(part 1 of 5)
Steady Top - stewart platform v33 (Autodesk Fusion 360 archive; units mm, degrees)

design "Steady Top - stewart platform" references "L servo horn", "Meanwell RSP-150-7.5", "815 Servo Driver 16 Channel", "KBRM_10_2", "KBRM_05_1", "fab dev board 2", "sunfounder_20kgSLDPRT", "GZRM_06_IG_6", "PCB mount", "KCRM_10_3", "R servo horn", "SERVO ARM HORN WITH FASTENERS", "BNO085 STEMMA QT", "Ball joint"
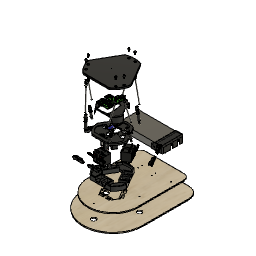
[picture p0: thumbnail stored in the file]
description: Part Number
part number: 7010K167_Power Supply
part number: 91292A191_18-8 Stainless Steel Socket Head Screw
description: STEP AP214
part number: 2025_05_17_16_39_25_0877
component_insert "Component Insert1"
position "Position1"
component_insert "Component Insert2"
position "Position2"
step "00000000-0000-0000-0000-000000000000" TotalAngle 360
sketch "Sketch1" plane through (0, 0, 0) normal (0, 0, 1) x axis (1, 0, 0)
  line L1 (25.1, -61.9) -> (-25.1, -61.9)
  line L2 (25.1, -33.65) -> (25.1, -61.9)
  line L3 (-25.1, -33.65) -> (25.1, -33.65)
  line L4 (-25.1, -61.9) -> (-25.1, -33.65)
  line L5 (0, 0) -> (0, -33.65)
  line L6 (-4.975, -61.9) -> (4.975, -61.9)
  line L7 (-4.975, -5.4) -> (-4.975, -61.9)
  line L8 (4.975, -5.4) -> (-4.975, -5.4)
  line L9 (4.975, -61.9) -> (4.975, -5.4)
  line L10 (-4.975, -5.4) -> (4.975, -61.9)
  line L11 (4.975, -5.4) -> (-4.975, -61.9)
  line L12 (-50.6793, -61.9) -> (-25.1, -61.9)
  line L13 (50.6793, -61.9) -> (25.1, -61.9)
  line L14 (-54.1368, -58.9) -> (54.1368, -58.9)
  line L15 (78.0773, -17.4338) -> (23.9405, 76.3338)
  line L16 (-23.9405, 76.3338) -> (-78.0773, -17.4338)
  line L17 (78.9466, -12.9395) -> (66.157, 9.2128)
  line L18 (28.2673, 74.8395) -> (41.057, 52.6872)
  line L19 (2.189, 7.0085) -> (7.164, -1.6085)
  line L20 (51.1195, 35.2585) -> (2.189, 7.0085)
  line L21 (7.164, -1.6085) -> (56.0945, 26.6415)
  line L22 (56.0945, 26.6415) -> (51.1195, 35.2585)
  line L23 (16.5918, 38.5622) -> (41.057, 52.6872)
  line L24 (66.157, 9.2128) -> (41.6918, -4.9122)
  line L25 (41.6918, -4.9122) -> (16.5918, 38.5622)
  line L26 (-28.2673, 74.8395) -> (-41.057, 52.6872)
  line L27 (-78.9466, -12.9395) -> (-66.157, 9.2128)
  line L28 (-7.164, -1.6085) -> (-2.189, 7.0085)
  line L29 (-56.0945, 26.6415) -> (-7.164, -1.6085)
  line L30 (-2.189, 7.0085) -> (-51.1195, 35.2585)
  line L31 (-51.1195, 35.2585) -> (-56.0945, 26.6415)
  line L32 (-41.6918, -4.9122) -> (-66.157, 9.2128)
  line L33 (-41.057, 52.6872) -> (-16.5918, 38.5622)
  line L34 (-16.5918, 38.5622) -> (-41.6918, -4.9122)
  line L35 (41.057, 52.6872) -> (66.157, 9.2128)
  line L36 (-66.157, 9.2128) -> (-41.057, 52.6872)
  circle C1 centre (0, 0) radius 80
  point P1 (0, 0)
  point P2 (0, 0)
  point P7 (0, -33.65)
  point P8 (0, 0)
  point P14 (0, -33.65)
  point P10 (4.975, -61.9)
  point P15 (-50.6793, -61.9)
  point P16 (50.6793, -61.9)
  point P17 (54.1368, -58.9)
  point P18 (-54.1368, -58.9)
  point P5 (25.1, -33.65)
  point P6 (-25.1, -33.65)
  point P9 (0, 0)
  point P12 (-4.975, -5.4)
  point P13 (4.975, -5.4)
  coincident P1 P2
  horizontal L1
  vertical L2
  horizontal L3
  vertical L4
  midpoint L3 P7
  coincident P1 P8
  vertical L5
  horizontal L6
  perpendicular L6 L7
  parallel L6 L8
  parallel L7 L9
  coincident L10 P14
  coincident L11 P14
  coincident L1 P10
  coincident P7 P14
  coincident C1 P15
  perpendicular L4 L12
  coincident C1 P16
  perpendicular L2 L13
  coincident C1 P17
  coincident C1 P18
  parallel L13 L14
  dimension "d3" diameter C1 = 160
  dimension "d4" distance P5 P6 = 50.2
  dimension "d5" distance L1 P8 = 61.9
  dimension "d6" distance L3 P9 = 33.65
  dimension "d7" distance P12 P13 = 9.95
  dimension "d8" distance L12 L14 = 3
  dimension "d10" C-Pattern1-Angle = 360
extrude "Extrude1" new body sketch "Sketch1" profile of C1 L1 L2 L3 L4 L5 L6 L7 L8 L9 L12 L13 L14 L15 L16 L17 L18 L19 L20 L21 L22 L23 L24 L25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 against normal blind 9.75
extrude "Extrude2" sketch "Sketch1" profile of C1 L1 L2 L3 L4 L5 L6 L7 L8 L9 L12 L13 L14 L15 L16 L17 L18 L19 L20 L21 L22 L23 L24 L25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 blind -9
shell "Shell1" innerThickness 5
sketch "Sketch2" plane through (0, 0, -9.75) normal (0, 0, 1) x axis (-1, 0, 0)
  line L1 (78.9466, 12.9395) -> (28.2673, -74.8395)
  line L2 (-50.6793, 61.9) -> (50.6793, 61.9)
  line L3 (-28.2673, -74.8395) -> (-78.9466, 12.9395)
  line L4 (-50.8068, 0) -> (-25.4034, 44)
  line L5 (-25.4034, -44) -> (-50.8068, 0)
  line L6 (25.4034, -44) -> (-25.4034, -44)
  line L7 (50.8068, 0) -> (25.4034, -44)
  line L8 (25.4034, 44) -> (50.8068, 0)
  line L9 (-25.4034, 44) -> (25.4034, 44)
  arc A1 centre (0, 0) radius 80 clockwise from (28.2673, -74.8395) to (-28.2673, -74.8395)
  arc A2 centre (0, 0) radius 80 clockwise from (50.6793, 61.9) to (78.9466, 12.9395)
  arc A3 centre (0, 0) radius 80 clockwise from (-78.9466, 12.9395) to (-50.6793, 61.9)
  point P4 (0, 0)
  point P15 (0, 0)
  coincident P4 P15
  dimension "d17" distance P4 L9 = 44
extrude "Extrude3" cut sketch "Sketch2" profile of L4 L5 L6 L7 L8 L9 against normal blind 9
combine "Combine1"
extrude "Extrude4" add of existing geometry to an object
sketch "Sketch3" plane through (0, -61.9, 0) normal (0, -1, 0) x axis (1, 0, 0)
  line L1 (-4.975, 0) -> (4.975, 0)
  line L2 (-4.975, -9.75) -> (-4.975, 0)
  line L3 (-25.1, -9.75) -> (-4.975, -9.75)
  line L4 (-25.1, 0) -> (-25.1, -9.75)
  line L5 (-50.6793, 0) -> (-25.1, 0)
  line L6 (-50.6793, -18.75) -> (-50.6793, 0)
  line L7 (50.6793, -18.75) -> (-50.6793, -18.75)
  line L8 (50.6793, 0) -> (50.6793, -18.75)
  line L9 (25.1, 0) -> (50.6793, 0)
  line L10 (25.1, -9.75) -> (25.1, 0)
  line L11 (4.975, -9.75) -> (25.1, -9.75)
  line L12 (4.975, 0) -> (4.975, -9.75)
  arc A1 centre (-19.75, 34.7974) radius 2.15 clockwise from (-18.85, 36.75) to (-20.65, 36.75)
  arc A2 centre (-19.75, 34.7974) radius 2.15 clockwise from (-18.85, 36.75) to (-20.65, 36.75)
  arc A3 centre (-10.25, 34.7974) radius 2.15 clockwise from (-9.35, 36.75) to (-11.15, 36.75)
  arc A4 centre (-10.25, 34.7974) radius 2.15 clockwise from (-9.35, 36.75) to (-11.15, 36.75)
  arc A5 centre (19.75, 34.7974) radius 2.15 clockwise from (20.65, 36.75) to (18.85, 36.75)
  arc A6 centre (19.75, 34.7974) radius 2.15 clockwise from (20.65, 36.75) to (18.85, 36.75)
  arc A7 centre (10.25, 34.7974) radius 2.15 clockwise from (11.15, 36.75) to (9.35, 36.75)
  arc A8 centre (10.25, 34.7974) radius 2.15 clockwise from (11.15, 36.75) to (9.35, 36.75)
  circle C1 centre (-10.25, 34.7974) radius 1.775
  circle C2 centre (-19.75, 34.7974) radius 1.775
  circle C3 centre (19.75, 34.7974) radius 1.775
  circle C4 centre (10.25, 34.7974) radius 1.775
  arc A9 centre (-19.75, -13.8974) radius 2.15 clockwise from (-20.65, -15.85) to (-18.85, -15.85)
  arc A10 centre (-19.75, -13.8974) radius 2.15 clockwise from (-20.65, -15.85) to (-18.85, -15.85)
  arc A11 centre (-10.25, -13.8974) radius 2.15 clockwise from (-11.15, -15.85) to (-9.35, -15.85)
  arc A12 centre (-10.25, -13.8974) radius 2.15 clockwise from (-11.15, -15.85) to (-9.35, -15.85)
  arc A13 centre (10.25, -13.8974) radius 2.15 clockwise from (9.35, -15.85) to (11.15, -15.85)
  arc A14 centre (10.25, -13.8974) radius 2.15 clockwise from (9.35, -15.85) to (11.15, -15.85)
  circle C5 centre (-19.75, -13.8974) radius 1.8
  circle C6 centre (-10.25, -13.8974) radius 1.8
  circle C7 centre (10.25, -13.8974) radius 1.8
  circle C8 centre (19.7639, -13.8974) radius 1.8
  concentric A3 C1
  concentric A1 C2
  concentric A5 C3
  concentric A7 C4
  equal C3 C4
  equal C2 C3
  equal C1 C2
  concentric A9 C5
  concentric A11 C6
  concentric A13 C7
  equal C7 C8
  equal C6 C7
  equal C5 C6
  dimension "d22" diameter C1 = 3.55
  dimension "d27" diameter C5 = 3.6
extrude "Extrude5" cut sketch "Sketch3" profile of C3 C5 C6 C7 C8 against normal blind 17.9
circular_pattern "C-Pattern1" TotalAngle 360
component_insert "Component Insert3"
position "Position3"
component_insert "Component Insert4"
joint "Assemble1" alignAngle 90 alignOffsetX 0 alignOffsetY 0 alignOffsetZ 0
component_insert "Component Insert5"
joint "Assemble2" alignAngle 270 alignOffsetX 0 alignOffsetY 0 alignOffsetZ 0
step "00000000-0000-0000-0000-000000000000" TotalAngle 360
work_plane "WorkPlane1" AlongDistance -80
sketch "Sketch4" plane through (0, 0, 100.9) normal (0, 0, -1) x axis (-1, 0, 0)
  line L1 (61.1061, 54.1611) -> (62.458, 51.8196)
  line L2 (63.7137, 52.5446) -> (62.458, 51.8196)
  line L3 (63.7137, 52.5446) -> (62.3618, 54.8861)
  line L4 (61.1061, 54.1611) -> (62.3618, 54.8861)
  line L5 (76.1061, 28.1804) -> (77.458, 25.8389)
  line L6 (78.7137, 26.5639) -> (77.458, 25.8389)
  line L7 (78.7137, 26.5639) -> (77.3618, 28.9054)
  line L8 (76.1061, 28.1804) -> (77.3618, 28.9054)
  line L9 (60.5533, 52.281) -> (61.782, 52.9904)
  line L10 (75.5533, 26.3002) -> (76.782, 27.0096)
  line L11 (60.5533, 52.281) -> (75.5533, 26.3002)
  line L12 (-75.5533, 26.3002) -> (-60.5533, 52.281)
  line L13 (15, -78.5812) -> (-15, -78.5812)
  line L14 (16.25, -88.5812) -> (13.75, -88.5812)
  line L15 (16.25, -68.5812) -> (16.25, -88.5812)
  line L16 (13.75, -68.5812) -> (16.25, -68.5812)
  line L17 (13.75, -88.5812) -> (13.75, -68.5812)
  line L18 (16.25, -68.5812) -> (13.75, -88.5812)
  line L19 (13.75, -68.5812) -> (16.25, -88.5812)
  line L20 (-16.25, -88.5812) -> (-13.75, -88.5812)
  line L21 (-16.25, -68.5812) -> (-16.25, -88.5812)
  line L22 (-13.75, -68.5812) -> (-16.25, -68.5812)
  line L23 (-13.75, -88.5812) -> (-13.75, -68.5812)
  line L24 (-16.25, -68.5812) -> (-13.75, -88.5812)
  line L25 (-13.75, -68.5812) -> (-16.25, -88.5812)
  line L26 (51.268, 48.3635) -> (68.5885, 58.3635)
  line L27 (52.518, 46.1984) -> (51.268, 48.3635)
  line L28 (68.5885, 58.3635) -> (69.8385, 56.1984)
  line L29 (69.8385, 56.1984) -> (52.518, 46.1984)
  line L30 (83.5885, 32.3827) -> (66.268, 22.3827)
  line L31 (84.8385, 30.2177) -> (83.5885, 32.3827)
  line L32 (66.268, 22.3827) -> (67.518, 20.2177)
  line L33 (67.518, 20.2177) -> (84.8385, 30.2177)
  line L34 (-67.518, 20.2177) -> (-84.8385, 30.2177)
  line L35 (-66.268, 22.3827) -> (-67.518, 20.2177)
  line L36 (-84.8385, 30.2177) -> (-83.5885, 32.3827)
  line L37 (-83.5885, 32.3827) -> (-66.268, 22.3827)
  line L38 (-69.8385, 56.1984) -> (-52.518, 46.1984)
  line L39 (-68.5885, 58.3635) -> (-69.8385, 56.1984)
  line L40 (-52.518, 46.1984) -> (-51.268, 48.3635)
  line L41 (-51.268, 48.3635) -> (-68.5885, 58.3635)
  circle C1 centre (0, 0) radius 80
  point P1 (0, 0)
  point P2 (0, 0)
  point P11 (61.782, 52.9904)
  point P12 (60.5533, 52.281)
  point P13 (76.782, 27.0096)
  point P14 (75.5533, 26.3002)
  point P23 (15, -78.5812)
  point P18 (15, -78.5812)
  point P28 (-15, -78.5812)
  point P17 (-15, -78.5812)
  point P19 (13.75, -88.5812)
  point P20 (16.25, -88.5812)
  point P22 (13.75, -68.5812)
  point P24 (-13.75, -88.5812)
  point P25 (-16.25, -88.5812)
  point P27 (-13.75, -68.5812)
  coincident P1 P2
  midpoint L1 P11
  coincident C1 P12
  perpendicular L1 L9
  midpoint L5 P13
  coincident C1 P14
  perpendicular L5 L10
  horizontal L14
  perpendicular L14 L15
  parallel L14 L16
  parallel L15 L17
  coincident L18 P23
  coincident L19 P23
  coincident P18 P23
  horizontal L20
  perpendicular L20 L21
  parallel L20 L22
  parallel L21 L23
  coincident L24 P28
  coincident L25 P28
  coincident P17 P28
  dimension "d39" diameter C1 = 160
  dimension "d43" distance P19 P20 = 2.5
  dimension "d44" distance P19 P22 = 20
  dimension "d45" distance P24 P25 = 2.5
  dimension "d46" distance P24 P27 = 20
  dimension "d42" C-Pattern1-Angle = 360
  dimension "d48" C-Pattern2-Angle = 360
extrude "Extrude6" new body sketch "Sketch4" profile of C1 L11 L12 L13 L15 L16 L17 L21 L22 L23 L26 L27 L29 L30 L32 L33 L34 L35 L37 L38 L40 L41 distance 2
move "Move1"
base_feature "Base Feature1"
position "Position4"
work_plane "WorkPlane2" AlongDistance 30.7
sketch "Sketch5" plane through (0, 0, 30.7) normal (0, 0, 1) x axis (1, 0, 0)
  line L1 (-64.3268, 2.3826) -> (-73.7073, -13.8648)
  line L2 (-39.8616, -11.7424) -> (-64.3268, 2.3826)
  line L3 (-9.7616, 40.3924) -> (-39.8616, -11.7424)
  line L4 (-34.2268, 54.5174) -> (-9.7616, 40.3924)
  line L5 (-24.8464, 70.7648) -> (-34.2268, 54.5174)
  line L6 (34.2268, 54.5174) -> (24.8464, 70.7648)
  line L7 (9.7616, 40.3924) -> (34.2268, 54.5174)
  line L8 (39.8616, -11.7424) -> (9.7616, 40.3924)
  line L9 (64.3268, 2.3826) -> (39.8616, -11.7424)
  line L10 (73.7073, -13.8648) -> (64.3268, 2.3826)
  line L11 (30.1, -56.9) -> (48.8609, -56.9)
  line L12 (30.1, -28.65) -> (30.1, -56.9)
  line L13 (-30.1, -28.65) -> (30.1, -28.65)
  line L14 (-30.1, -56.9) -> (-30.1, -28.65)
  line L15 (-48.8609, -56.9) -> (-30.1, -56.9)
  line L16 (-78.9466, -12.9395) -> (-66.157, 9.2128)
  line L17 (-25.1, -61.9) -> (-50.6793, -61.9)
  line L18 (-25.1, -33.65) -> (-25.1, -61.9)
  line L19 (-4.975, -33.65) -> (-25.1, -33.65)
  line L20 (-4.975, -61.9) -> (-4.975, -33.65)
  line L21 (4.975, -61.9) -> (-4.975, -61.9)
  line L22 (4.975, -33.65) -> (4.975, -61.9)
  line L23 (25.1, -33.65) -> (4.975, -33.65)
  line L24 (25.1, -61.9) -> (25.1, -33.65)
  line L25 (50.6793, -61.9) -> (25.1, -61.9)
  line L26 (66.157, 9.2128) -> (78.9466, -12.9395)
  line L27 (41.6918, -4.9122) -> (66.157, 9.2128)
  line L28 (31.6293, 12.5165) -> (41.6918, -4.9122)
  line L29 (56.0945, 26.6415) -> (31.6293, 12.5165)
  line L30 (51.1195, 35.2585) -> (56.0945, 26.6415)
  line L31 (26.6543, 21.1335) -> (51.1195, 35.2585)
  line L32 (16.5918, 38.5622) -> (26.6543, 21.1335)
  line L33 (41.057, 52.6872) -> (16.5918, 38.5622)
  line L34 (28.2673, 74.8395) -> (41.057, 52.6872)
  line L35 (-41.057, 52.6872) -> (-28.2673, 74.8395)
  line L36 (-16.5918, 38.5622) -> (-41.057, 52.6872)
  line L37 (-26.6543, 21.1335) -> (-16.5918, 38.5622)
  line L38 (-51.1195, 35.2585) -> (-26.6543, 21.1335)
  line L39 (-56.0945, 26.6415) -> (-51.1195, 35.2585)
  line L40 (-31.6293, 12.5165) -> (-56.0945, 26.6415)
  line L41 (-41.6918, -4.9122) -> (-31.6293, 12.5165)
  line L42 (-66.157, 9.2128) -> (-41.6918, -4.9122)
  line L43 (-25.1, -61.9) -> (25.1, -61.9)
  line L44 (-25.1, -47.775) -> (-25.1, -61.9)
  line L45 (25.1, -47.775) -> (-25.1, -47.775)
  line L46 (25.1, -61.9) -> (25.1, -47.775)
  line L47 (-41.057, 52.6872) -> (-66.157, 9.2128)
  line L48 (-28.8244, 45.6247) -> (-41.057, 52.6872)
  line L49 (-53.9244, 2.1503) -> (-28.8244, 45.6247)
  line L50 (-66.157, 9.2128) -> (-53.9244, 2.1503)
  line L51 (66.157, 9.2128) -> (41.057, 52.6872)
  line L52 (53.9244, 2.1503) -> (66.157, 9.2128)
  line L53 (28.8244, 45.6247) -> (53.9244, 2.1503)
  line L54 (41.057, 52.6872) -> (28.8244, 45.6247)
  line L55 (-9.734, -26.7646) -> (9.316, -26.7646)
  line L56 (-12.909, 32.2904) -> (-12.909, -23.5896)
  line L57 (9.316, 35.4654) -> (-9.734, 35.4654)
  line L58 (12.491, -23.5896) -> (12.491, 32.2904)
  line L59 (-10.0375, -41.15) -> (-20.0375, -41.15)
  line L60 (-10.0375, -26.15) -> (-10.0375, -41.15)
  line L61 (-20.0375, -26.15) -> (-10.0375, -26.15)
  line L62 (-20.0375, -41.15) -> (-20.0375, -26.15)
  line L63 (-10.0375, -26.15) -> (-20.0375, -41.15)
  line L64 (-20.0375, -26.15) -> (-10.0375, -41.15)
  line L65 (10.0375, -41.15) -> (20.0375, -41.15)
  line L66 (10.0375, -26.15) -> (10.0375, -41.15)
  line L67 (20.0375, -26.15) -> (10.0375, -26.15)
  line L68 (20.0375, -41.15) -> (20.0375, -26.15)
  line L69 (10.0375, -26.15) -> (20.0375, -41.15)
  line L70 (20.0375, -26.15) -> (10.0375, -41.15)
  line L71 (45.6557, 3.222) -> (32.6653, -4.278)
  line L72 (40.6557, 11.8823) -> (45.6557, 3.222)
  line L73 (32.6653, -4.278) -> (27.6653, 4.3823)
  line L74 (27.6653, 4.3823) -> (40.6557, 11.8823)
  line L75 (17.6278, 21.7677) -> (30.6182, 29.2677)
  line L76 (12.6278, 30.428) -> (17.6278, 21.7677)
  line L77 (30.6182, 29.2677) -> (25.6182, 37.928)
  line L78 (25.6182, 37.928) -> (12.6278, 30.428)
  line L79 (-25.6182, 37.928) -> (-12.6278, 30.428)
  line L80 (-30.6182, 29.2677) -> (-25.6182, 37.928)
  line L81 (-12.6278, 30.428) -> (-17.6278, 21.7677)
  line L82 (-17.6278, 21.7677) -> (-30.6182, 29.2677)
  line L83 (-27.6653, 4.3823) -> (-40.6557, 11.8823)
  line L84 (-32.6653, -4.278) -> (-27.6653, 4.3823)
  line L85 (-40.6557, 11.8823) -> (-45.6557, 3.222)
  line L86 (-45.6557, 3.222) -> (-32.6653, -4.278)
  arc A1 centre (0, 0) radius 75 clockwise from (-48.8609, -56.9) to (-73.7073, -13.8648)
  arc A2 centre (0, 0) radius 75 clockwise from (-24.8464, 70.7648) to (24.8464, 70.7648)
  arc A3 centre (0, 0) radius 75 clockwise from (73.7073, -13.8648) to (48.8609, -56.9)
  arc A4 centre (0, 0) radius 80 clockwise from (-50.6793, -61.9) to (-78.9466, -12.9395)
  arc A5 centre (0, 0) radius 80 clockwise from (78.9466, -12.9395) to (50.6793, -61.9)
  arc A6 centre (0, 0) radius 80 clockwise from (-28.2673, 74.8395) to (28.2673, 74.8395)
  circle C1 centre (-11.512, -1.9996) radius 0.5
  circle C2 centre (-11.512, -7.0796) radius 0.5
  circle C3 centre (-6.432, 0.5404) radius 0.5
  circle C4 centre (-6.432, -1.9996) radius 0.5
  circle C5 centre (-6.432, -4.5396) radius 0.5
  circle C6 centre (-6.432, -7.0796) radius 0.5
  circle C7 centre (-11.512, -14.6996) radius 0.5
  circle C8 centre (-11.512, -19.7796) radius 0.5
  circle C9 centre (-6.432, -12.1596) radius 0.5
  circle C10 centre (-6.432, -14.6996) radius 0.5
  circle C11 centre (-6.432, -17.2396) radius 0.5
  circle C12 centre (-6.432, -19.7796) radius 0.5
  circle C13 centre (-11.512, 25.9404) radius 0.5
  circle C14 centre (-11.512, 20.8604) radius 0.5
  circle C15 centre (-6.432, 28.4804) radius 0.5
  circle C16 centre (-6.432, 25.9404) radius 0.5
  circle C17 centre (-6.432, 23.4004) radius 0.5
  circle C18 centre (-6.432, 20.8604) radius 0.5
  circle C19 centre (-11.512, 13.2404) radius 0.5
  circle C20 centre (-11.512, 8.1604) radius 0.5
  circle C21 centre (-6.432, 15.7804) radius 0.5
  circle C22 centre (-6.432, 13.2404) radius 0.5
  circle C23 centre (-6.432, 10.7004) radius 0.5
  circle C24 centre (-8.972, 18.3204) radius 0.25
  circle C25 centre (6.268, -24.8596) radius 0.508
  circle C26 centre (1.188, -24.8596) radius 0.508
  circle C27 centre (-3.892, -24.8596) radius 0.508
  circle C28 centre (6.268, 33.5604) radius 0.508
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  point P53 (-25.1, -47.775)
  point P31 (25.1, -61.9)
  point P51 (25.1, -61.9)
  point P44 (-41.057, 52.6872)
  point P56 (-41.057, 52.6872)
  point P21 (-66.157, 9.2128)
  point P55 (-66.157, 9.2128)
  point P34 (66.157, 9.2128)
  point P60 (66.157, 9.2128)
  point P41 (41.057, 52.6872)
  point P59 (41.057, 52.6872)
  point P170 (-15.0375, -33.65)
  point P175 (15.0375, -33.65)
  point P162 (-9.734, 35.4654)
  point P193 (-9.734, 35.4654)
  point P161 (-12.909, 32.2904)
  point P192 (-12.909, 32.2904)
  point P164 (12.491, 32.2904)
  point P196 (12.491, 32.2904)
  point P163 (9.316, 35.4654)
  point P195 (9.316, 35.4654)
  point P159 (-9.734, -26.7646)
  point P199 (-9.734, -26.7646)
  point P160 (-12.909, -23.5896)
  point P198 (-12.909, -23.5896)
  point P165 (12.491, -23.5896)
  point P202 (12.491, -23.5896)
  point P158 (9.316, -26.7646)
  point P201 (9.316, -26.7646)
  point P166 (-20.0375, -41.15)
  point P167 (-10.0375, -41.15)
  point P169 (-20.0375, -26.15)
  point P171 (20.0375, -41.15)
  point P172 (10.0375, -41.15)
  point P174 (20.0375, -26.15)
  horizontal L43
  vertical L44
  horizontal L45
  vertical L46
  midpoint L18 P53
  coincident P31 P51
  perpendicular L47 L48
  parallel L47 L49
  parallel L48 L50
  coincident P44 P56
  perpendicular L36 L47
  coincident P21 P55
  perpendicular L51 L52
  parallel L51 L53
  parallel L52 L54
  coincident P34 P60
  perpendicular L27 L51
  coincident P41 P59
  horizontal L59
  perpendicular L59 L60
  parallel L59 L61
  parallel L60 L62
  coincident L63 P170
  coincident L64 P170
  midpoint L19 P170
  horizontal L65
  perpendicular L65 L66
  parallel L65 L67
  parallel L66 L68
  coincident L69 P175
  coincident L70 P175
  midpoint L23 P175
  coincident P162 P193
  coincident P161 P192
  coincident P164 P196
  coincident P163 P195
  coincident P159 P199
  coincident P160 P198
  coincident P165 P202
  coincident P158 P201
  dimension "d54" distance P166 P167 = 10
  dimension "d55" distance P166 P169 = 15
  dimension "d56" distance P171 P172 = 10
  dimension "d57" distance P171 P174 = 15
  dimension "d59" C-Pattern1-Angle = 360
extrude "Extrude7" new body sketch "Sketch5" along normal blind 7
fillet "Fillet1" radius 1
sketch "Sketch6" plane through (0, 0, 37.7) normal (0, 0, 1) x axis (-1, 0, 0)
  line L1 (10.0375, 33.65) -> (10.0375, 28.65)
  line L2 (4.975, 33.65) -> (10.0375, 33.65)
  line L3 (4.975, 47.775) -> (4.975, 33.65)
  line L4 (25.1, 47.775) -> (4.975, 47.775)
  line L5 (25.1, 33.65) -> (25.1, 47.775)
  line L6 (20.0375, 33.65) -> (25.1, 33.65)
  line L7 (20.0375, 28.65) -> (20.0375, 33.65)
  line L8 (10.0375, 28.65) -> (20.0375, 28.65)
  line L9 (-12.491, 20.7277) -> (-12.491, -29.4458)
  line L10 (6.6939, 26.7646) -> (-6.454, 26.7646)
  line L11 (12.909, -29.3521) -> (12.909, 20.5494)
  line L12 (-6.4713, -35.4654) -> (6.7957, -35.4654)
  line L13 (-29.8304, -5.6323) -> (-34.8304, 3.028)
  line L14 (-34.1605, -8.1323) -> (-29.8304, -5.6323)
  line L15 (-31.6293, -12.5165) -> (-34.1605, -8.1323)
  line L16 (-43.8619, -19.579) -> (-31.6293, -12.5165)
  line L17 (-53.9244, -2.1503) -> (-43.8619, -19.579)
  line L18 (-41.6918, 4.9122) -> (-53.9244, -2.1503)
  line L19 (-39.1605, 0.528) -> (-41.6918, 4.9122)
  line L20 (-34.8304, 3.028) -> (-39.1605, 0.528)
  line L21 (-19.123, -34.178) -> (-14.7929, -31.678)
  line L22 (-16.5918, -38.5622) -> (-19.123, -34.178)
  line L23 (-28.8244, -45.6247) -> (-16.5918, -38.5622)
  line L24 (-38.8869, -28.196) -> (-28.8244, -45.6247)
  line L25 (-26.6543, -21.1335) -> (-38.8869, -28.196)
  line L26 (-24.123, -25.5177) -> (-26.6543, -21.1335)
  line L27 (-19.7929, -23.0177) -> (-24.123, -25.5177)
  line L28 (-14.7929, -31.678) -> (-19.7929, -23.0177)
  line L29 (-20.0375, 33.65) -> (-20.0375, 28.65)
  line L30 (-25.1, 33.65) -> (-20.0375, 33.65)
  line L31 (-25.1, 47.775) -> (-25.1, 33.65)
  line L32 (-4.975, 47.775) -> (-25.1, 47.775)
  line L33 (-4.975, 33.65) -> (-4.975, 47.775)
  line L34 (-10.0375, 33.65) -> (-4.975, 33.65)
  line L35 (-10.0375, 28.65) -> (-10.0375, 33.65)
  line L36 (-20.0375, 28.65) -> (-10.0375, 28.65)
  line L37 (39.1605, 0.528) -> (34.8304, 3.028)
  line L38 (41.6918, 4.9122) -> (39.1605, 0.528)
  line L39 (53.9244, -2.1503) -> (41.6918, 4.9122)
  line L40 (43.8619, -19.579) -> (53.9244, -2.1503)
  line L41 (31.6293, -12.5165) -> (43.8619, -19.579)
  line L42 (34.1605, -8.1323) -> (31.6293, -12.5165)
  line L43 (29.8304, -5.6323) -> (34.1605, -8.1323)
  line L44 (34.8304, 3.028) -> (29.8304, -5.6323)
  line L45 (19.7929, -23.0177) -> (14.7929, -31.678)
  line L46 (24.123, -25.5177) -> (19.7929, -23.0177)
  line L47 (26.6543, -21.1335) -> (24.123, -25.5177)
  line L48 (38.8869, -28.196) -> (26.6543, -21.1335)
  line L49 (28.8244, -45.6247) -> (38.8869, -28.196)
  line L50 (16.5918, -38.5622) -> (28.8244, -45.6247)
  line L51 (19.123, -34.178) -> (16.5918, -38.5622)
  line L52 (14.7929, -31.678) -> (19.123, -34.178)
  line L53 (78.9466, 12.9395) -> (28.2673, -74.8395)
  line L54 (-50.6793, 61.9) -> (50.6793, 61.9)
  line L55 (-28.2673, -74.8395) -> (-78.9466, 12.9395)
  line L56 (12.909, -29.3521) -> (12.909, 20.5494)
  line L57 (6.6939, 26.7646) -> (-6.454, 26.7646)
  line L58 (-12.491, 20.7277) -> (-12.491, -29.4458)
  line L59 (-6.4713, -35.4654) -> (6.7957, -35.4654)
  line L60 (14.7929, -31.678) -> (19.123, -34.178)
  line L61 (19.123, -34.178) -> (16.5918, -38.5622)
  line L62 (16.5918, -38.5622) -> (28.8244, -45.6247)
  line L63 (28.8244, -45.6247) -> (38.8869, -28.196)
  line L64 (38.8869, -28.196) -> (26.6543, -21.1335)
  line L65 (26.6543, -21.1335) -> (24.123, -25.5177)
  line L66 (24.123, -25.5177) -> (19.7929, -23.0177)
  line L67 (19.7929, -23.0177) -> (14.7929, -31.678)
  line L68 (34.8304, 3.028) -> (29.8304, -5.6323)
  line L69 (29.8304, -5.6323) -> (34.1605, -8.1323)
  line L70 (34.1605, -8.1323) -> (31.6293, -12.5165)
  line L71 (31.6293, -12.5165) -> (43.8619, -19.579)
  line L72 (43.8619, -19.579) -> (53.9244, -2.1503)
  line L73 (53.9244, -2.1503) -> (41.6918, 4.9122)
  line L74 (41.6918, 4.9122) -> (39.1605, 0.528)
  line L75 (39.1605, 0.528) -> (34.8304, 3.028)
  line L76 (-20.0375, 28.65) -> (-10.0375, 28.65)
  line L77 (-10.0375, 28.65) -> (-10.0375, 33.65)
  line L78 (-10.0375, 33.65) -> (-4.975, 33.65)
  line L79 (-4.975, 33.65) -> (-4.975, 47.775)
  line L80 (-4.975, 47.775) -> (-25.1, 47.775)
  line L81 (-25.1, 47.775) -> (-25.1, 33.65)
  line L82 (-25.1, 33.65) -> (-20.0375, 33.65)
  line L83 (-20.0375, 33.65) -> (-20.0375, 28.65)
  line L84 (-14.7929, -31.678) -> (-19.7929, -23.0177)
  line L85 (-19.7929, -23.0177) -> (-24.123, -25.5177)
  line L86 (-24.123, -25.5177) -> (-26.6543, -21.1335)
  line L87 (-26.6543, -21.1335) -> (-38.8869, -28.196)
  line L88 (-38.8869, -28.196) -> (-28.8244, -45.6247)
  line L89 (-28.8244, -45.6247) -> (-16.5918, -38.5622)
  line L90 (-16.5918, -38.5622) -> (-19.123, -34.178)
  line L91 (-19.123, -34.178) -> (-14.7929, -31.678)
  line L92 (-34.8304, 3.028) -> (-39.1605, 0.528)
  line L93 (-39.1605, 0.528) -> (-41.6918, 4.9122)
  line L94 (-41.6918, 4.9122) -> (-53.9244, -2.1503)
  line L95 (-53.9244, -2.1503) -> (-43.8619, -19.579)
  line L96 (-43.8619, -19.579) -> (-31.6293, -12.5165)
  line L97 (-31.6293, -12.5165) -> (-34.1605, -8.1323)
  line L98 (-34.1605, -8.1323) -> (-29.8304, -5.6323)
  line L99 (-29.8304, -5.6323) -> (-34.8304, 3.028)
  line L100 (10.0375, 28.65) -> (20.0375, 28.65)
  line L101 (20.0375, 28.65) -> (20.0375, 33.65)
  line L102 (20.0375, 33.65) -> (25.1, 33.65)
  line L103 (25.1, 33.65) -> (25.1, 47.775)
  line L104 (25.1, 47.775) -> (4.975, 47.775)
  line L105 (4.975, 47.775) -> (4.975, 33.65)
  line L106 (4.975, 33.65) -> (10.0375, 33.65)
  line L107 (10.0375, 33.65) -> (10.0375, 28.65)
  line L108 (-28.2673, -74.8395) -> (-78.9466, 12.9395)
  line L109 (-50.6793, 61.9) -> (50.6793, 61.9)
  line L110 (78.9466, 12.9395) -> (28.2673, -74.8395)
  line L111 (-18.6803, -63.1448) -> (-64.0252, 15.3948)
  line L112 (64.0252, 15.3948) -> (18.6803, -63.1448)
  line L113 (-45.3449, 47.75) -> (45.3449, 47.75)
  circle C1 centre (-9.316, 23.5896) radius 1.25
  circle C2 centre (9.734, -32.2904) radius 1.25
  circle C3 centre (-9.316, -32.2904) radius 1.25
  arc A1 centre (-11.491, 20.7277) radius 1 clockwise from (-12.491, 20.7277) to (-11.0361, 21.6182)
  arc A2 centre (-9.7881, 24.0617) radius 2.7438 clockwise from (-7.3446, 25.3097) to (-11.0361, 21.6182)
  arc A3 centre (-6.454, 25.7646) radius 1 clockwise from (-7.3446, 25.3097) to (-6.454, 26.7646)
  arc A4 centre (6.6939, 25.7646) radius 1 clockwise from (6.6939, 26.7646) to (7.5739, 25.2897)
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  dimension "d62" = -14.15
extrude "Extrude8" cut sketch "Sketch6" against normal blind 4
sketch "Sketch7" plane through (-53.607, 30.95, 0) normal (-0.866, 0.5, 0) x axis (-0.5, -0.866, 0)
  line L1 (50.6793, 30.7) -> (-50.6793, 30.7)
  line L2 (50.6793, 37.7) -> (50.6793, 30.7)
  line L3 (-50.6793, 37.7) -> (50.6793, 37.7)
  line L4 (-50.6793, 30.7) -> (-50.6793, 37.7)
  line L5 (17.0212, 30.7) -> (14.5212, 30.7)
  line L6 (29.8304, 30.7) -> (34.1605, 30.7)
  line L7 (34.8304, 30.7) -> (29.8304, 30.7)
  line L8 (39.1605, 30.7) -> (34.8304, 30.7)
  line L9 (41.6918, 30.7) -> (39.1605, 30.7)
  line L10 (53.9244, 30.7) -> (41.6918, 30.7)
  line L11 (43.8619, 30.7) -> (53.9244, 30.7)
  line L12 (31.6293, 30.7) -> (43.8619, 30.7)
  line L13 (34.1605, 30.7) -> (31.6293, 30.7)
  line L14 (-21.8473, 30.7) -> (-24.3473, 30.7)
  line L15 (-31.3723, 30.7) -> (-33.8723, 30.7)
  line L16 (-31.7463, 30.7) -> (-32.2463, 30.7)
  line L17 (-33.1373, 30.7) -> (-30.5504, 30.7)
  line L18 (-33.1373, 30.7) -> (-34.0836, 30.7)
  line L19 (-27.3161, 30.7) -> (-33.9496, 30.7)
  line L20 (-25.6055, 30.7) -> (-27.3161, 30.7)
  line L21 (-25.6055, 30.7) -> (-20.4643, 30.7)
  line L22 (-18.9651, 30.7) -> (-20.4643, 30.7)
  line L23 (24.2508, 30.7) -> (-18.9651, 30.7)
  line L24 (24.7508, 30.7) -> (24.2508, 30.7)
  line L25 (22.9214, 30.7) -> (25.6885, 30.7)
  line L26 (26.6597, 30.7) -> (25.6885, 30.7)
  line L27 (19.9518, 30.7) -> (26.5257, 30.7)
  line L28 (19.9518, 30.7) -> (18.2466, 30.7)
  line L29 (13.2039, 30.7) -> (18.2466, 30.7)
  line L30 (13.2039, 30.7) -> (11.7052, 30.7)
  line L31 (-31.7463, 30.7) -> (11.7052, 30.7)
  line L32 (-14.7929, 30.7) -> (-19.7929, 30.7)
  line L33 (-19.123, 30.7) -> (-14.7929, 30.7)
  line L34 (-16.5918, 30.7) -> (-19.123, 30.7)
  line L35 (-28.8244, 30.7) -> (-16.5918, 30.7)
  line L36 (-38.8869, 30.7) -> (-28.8244, 30.7)
  line L37 (-26.6543, 30.7) -> (-38.8869, 30.7)
  line L38 (-24.123, 30.7) -> (-26.6543, 30.7)
  line L39 (-19.7929, 30.7) -> (-24.123, 30.7)
  line L40 (-34.8304, 30.7) -> (-39.1605, 30.7)
  line L41 (-29.8304, 30.7) -> (-34.8304, 30.7)
  line L42 (-34.1605, 30.7) -> (-29.8304, 30.7)
  line L43 (-31.6293, 30.7) -> (-34.1605, 30.7)
  line L44 (-43.8619, 30.7) -> (-31.6293, 30.7)
  line L45 (-53.9244, 30.7) -> (-43.8619, 30.7)
  line L46 (-41.6918, 30.7) -> (-53.9244, 30.7)
  line L47 (-39.1605, 30.7) -> (-41.6918, 30.7)
  line L48 (26.5462, 30.7) -> (24.0462, 30.7)
  line L49 (14.7929, 30.7) -> (19.123, 30.7)
  line L50 (19.7929, 30.7) -> (14.7929, 30.7)
  line L51 (24.123, 30.7) -> (19.7929, 30.7)
  line L52 (26.6543, 30.7) -> (24.123, 30.7)
  line L53 (38.8869, 30.7) -> (26.6543, 30.7)
  line L54 (28.8244, 30.7) -> (38.8869, 30.7)
  line L55 (16.5918, 30.7) -> (28.8244, 30.7)
  line L56 (19.123, 30.7) -> (16.5918, 30.7)
  line L57 (10.0375, 30.7) -> (20.0375, 30.7)
  line L58 (4.975, 30.7) -> (10.0375, 30.7)
  line L59 (25.1, 30.7) -> (4.975, 30.7)
  line L60 (20.0375, 30.7) -> (25.1, 30.7)
  line L61 (-20.0375, 30.7) -> (-10.0375, 30.7)
  line L62 (-25.1, 30.7) -> (-20.0375, 30.7)
  line L63 (-4.975, 30.7) -> (-25.1, 30.7)
  line L64 (-10.0375, 30.7) -> (-4.975, 30.7)
  line L65 (-78.9466, 30.7) -> (-50.6793, 30.7)
  line L66 (-28.2673, 30.7) -> (-78.9466, 30.7)
  line L67 (-28.2673, 30.7) -> (28.2673, 30.7)
  line L68 (78.9466, 30.7) -> (28.2673, 30.7)
  line L69 (50.6793, 30.7) -> (78.9466, 30.7)
  line L70 (-50.6793, 30.7) -> (50.6793, 30.7)
  arc A1 centre (-19.75, 34.7974) radius 2.15 clockwise from (-18.85, 36.75) to (-20.65, 36.75)
  arc A2 centre (-19.75, 34.7974) radius 2.15 clockwise from (-18.85, 36.75) to (-20.65, 36.75)
  arc A3 centre (-10.25, 34.7974) radius 2.15 clockwise from (-9.35, 36.75) to (-11.15, 36.75)
  arc A4 centre (-10.25, 34.7974) radius 2.15 clockwise from (-9.35, 36.75) to (-11.15, 36.75)
  arc A5 centre (10.25, 34.7974) radius 2.15 clockwise from (11.15, 36.75) to (9.35, 36.75)
  arc A6 centre (10.25, 34.7974) radius 2.15 clockwise from (11.15, 36.75) to (9.35, 36.75)
  arc A7 centre (19.75, 34.7974) radius 2.15 clockwise from (20.65, 36.75) to (18.85, 36.75)
  arc A8 centre (19.75, 34.7974) radius 2.15 clockwise from (20.65, 36.75) to (18.85, 36.75)
  circle C1 centre (-19.75, 34.7974) radius 1.75
  circle C2 centre (-10.25, 34.7974) radius 1.75
  circle C3 centre (10.25, 34.7974) radius 1.75
  circle C4 centre (19.75, 34.7974) radius 1.75
  concentric A1 C1
  concentric A3 C2
  concentric A5 C3
  concentric A7 C4
  equal C3 C4
  equal C2 C3
  equal C1 C2
  dimension "d65" diameter C3 = 3.5
extrude "Extrude9" cut sketch "Sketch7" profile of C1 C2 C3 C4 against normal blind 14.125
circular_pattern "C-Pattern2" TotalAngle 360
extrude "Extrude10" add sketch "Sketch6" to an object
chamfer "Chamfer1" distance 0.5
position "Position5"
sketch "Sketch8" plane through (0, -80, 0) normal (0, -1, 0) x axis (1, 0, 0)
  circle C1 centre (15, 20.9) radius 2.6191
  circle C2 centre (15, 20.9) radius 1.9
  circle C3 centre (15, 20.9) radius 7.0856
  concentric C1 C3
extrude "Extrude11" new body sketch "Sketch8" against normal blind 4.048 and along normal blind 3.6043
sketch "Sketch9" plane through (0, -83.6043, 0) normal (0, -1, 0) x axis (1, 0, 0)
  line L1 (11.2563, 29.1736) -> (18.7437, 29.1736)
  line L2 (11.2563, 12.6264) -> (11.2563, 29.1736)
  line L3 (18.7437, 12.6264) -> (11.2563, 12.6264)
  line L4 (18.7437, 29.1736) -> (18.7437, 12.6264)
  line L5 (11.2563, 12.6264) -> (18.7437, 29.1736)
  line L6 (18.7437, 12.6264) -> (11.2563, 29.1736)
  line L7 (15, 29.1736) -> (15, 20.9)
  line L8 (7.1262, 28.2673) -> (22.8738, 28.2673)
  line L9 (7.1262, 13.5327) -> (7.1262, 28.2673)
  line L10 (22.8738, 13.5327) -> (7.1262, 13.5327)
  line L11 (22.8738, 28.2673) -> (22.8738, 13.5327)
  line L12 (7.1262, 13.5327) -> (22.8738, 28.2673)
  line L13 (22.8738, 13.5327) -> (7.1262, 28.2673)
  circle C1 centre (15, 20.9) radius 1.9
  circle C2 centre (15, 20.9) radius 7.0856
  point P7 (15, 20.9)
  point P2 (15, 20.9)
  point P8 (15, 20.9)
  point P9 (15, 29.1736)
  point P14 (15, 20.9)
  horizontal L1
  perpendicular L1 L2
  parallel L1 L3
  parallel L2 L4
  coincident L5 P7
  coincident L6 P7
  coincident P2 P7
  coincident P7 P8
  midpoint L1 P9
  horizontal L8
  perpendicular L8 L9
  parallel L8 L10
  parallel L9 L11
  coincident L12 P14
  coincident L13 P14
  coincident P7 P14
extrude "Extrude12" cut sketch "Sketch9" profile of C1 C2 L2 L4 L8 L9 L10 L11 against normal blind 3.082
chamfer "Chamfer2" distance 3.08
combine "Combine2"
copy_paste_bodies "CopyPasteBodies1"
work_plane "WorkPlane3" AlongDistance -100
sketch "Sketch10" plane through (0, 0, 120.9) normal (0, 0, -1) x axis (-1, 0, 0)
  line L1 (-64.9519, -82.5) -> (64.9519, -82.5)
  line L2 (103.923, -15) -> (38.9711, 97.5)
  line L3 (-38.9711, 97.5) -> (-103.923, -15)
  line L4 (-15, -102.5) -> (-15, -81.75)
  line L5 (15, -102.5) -> (15, -81.75)
  line L6 (-15, -103.923) -> (-15, -81.75)
  line L7 (15, -103.923) -> (15, -81.75)
  line L8 (97.5, -38.9711) -> (78.2976, -27.8846)
  line L9 (82.5, -64.9519) -> (63.2976, -53.8654)
  line L10 (-15, 103.923) -> (-15, 81.75)
  line L11 (15, 103.923) -> (15, 81.75)
  line L12 (-82.5, -64.9519) -> (-63.2976, -53.8654)
  line L13 (-97.5, -38.9711) -> (-78.2976, -27.8846)
  circle C1 centre (0, 0) radius 105
  circle C2 centre (72.8988, -59.4086) radius 5
  circle C3 centre (87.8988, -33.4279) radius 5
  point P1 (0, 0)
  point P2 (0, 0)
  point P3 (64.9519, -82.5)
  point P4 (-64.9519, -82.5)
  point P9 (-15, -81.75)
  point P13 (-15, -81.75)
  point P14 (-15, -103.923)
  point P11 (15, -81.75)
  point P15 (15, -81.75)
  point P16 (15, -103.923)
  point P29 (72.8988, -59.4086)
  point P30 (87.8988, -33.4279)
  coincident P1 P2
  coincident C1 P3
  coincident C1 P4
  horizontal L1
  coincident P9 P13
  coincident C1 P14
  perpendicular L1 L6
  coincident P11 P15
  coincident C1 P16
  parallel L5 L7
  midpoint L9 P29
  midpoint L8 P30
  equal C2 C3
  dimension "d81" diameter C1 = 210
  dimension "d82" distance P2 L1 = 82.5
  dimension "d87" diameter C2 = 10
  dimension "d84" C-Pattern1-Angle = 360
  dimension "d86" C-Pattern2-Angle = 360
revolve "Revolve1" sketch "Sketch10" AlongAngle 360
revolve "Revolve2" sketch "Sketch10" AlongAngle 360
extrude "Extrude13" new body sketch "Sketch10" profile of C1 L1 L2 L3 L8 L9 C2 C3 distance 8
sketch "Sketch11" plane through (0, 0, 116.9) normal (0, 0, -1) x axis (1, 0, 0)
  line L1 (-38.9711, -97.5) -> (-103.923, 15)
  line L2 (103.923, 15) -> (38.9711, -97.5)
  line L3 (-64.9519, 82.5) -> (64.9519, 82.5)
  arc A1 centre (0, 0) radius 105 clockwise from (-103.923, 15) to (-64.9519, 82.5)
  arc A2 centre (0, 0) radius 105 clockwise from (38.9711, -97.5) to (-38.9711, -97.5)
  arc A3 centre (0, 0) radius 105 clockwise from (64.9519, 82.5) to (103.923, 15)
  circle C1 centre (-72.8988, 59.4086) radius 5
  circle C2 centre (0, 0) radius 94.0405
  point P9 (-72.8988, 59.4086)
  concentric A1 C2
  coincident P9 C2
combine "Combine3"
chamfer "Chamfer3" distance 5 distance 2
split "Split1"
sketch "Sketch12" plane through (0, 0, 124.9) normal (0, 0, 1) x axis (-1, 0, 0)
  circle C1 centre (87.8988, 33.4279) radius 3
  circle C2 centre (87.8988, 33.4279) radius 1
  circle C3 centre (87.8988, 33.4279) radius 1.75
  concentric C1 C2
  concentric C2 C3
  dimension "d94" diameter C2 = 2
  dimension "d95" diameter C3 = 3.5
extrude "Extrude14" new body sketch "Sketch12" against normal blind 20
combine "Combine4"
sketch "Sketch13" plane through (0, -82.6, 0) normal (0, -1, 0) x axis (1, 0, 0)
  line L1 (-7.8294, 21.55) -> (-11.1038, 21.55)
  line L2 (-39, 24.05) -> (-27, 24.05)
  line L3 (-27, 17.75) -> (-39, 17.75)
  line L4 (-11.1038, 20.25) -> (-7.8294, 20.25)
  line L5 (-22.6481, 20.25) -> (-18.8962, 20.25)
  line L6 (-18.8962, 21.55) -> (-22.6481, 21.55)
  curve K1 (-35, 19.65) -> (-33.5903, 21.4702)
  curve K2 (-34.4103, 22.3016) -> (-36.25, 20.9)
  curve K3 (-39, 19.65) -> (-37.5903, 21.4702)
  curve K4 (-38.4103, 22.3016) -> (-40.25, 20.9)
  curve K5 (-29.1752, 21.9441) -> (-30.1237, 22.4749)
  line L7 (-30.45, 22.7971) -> (-30.1237, 22.4749)
  line L8 (-30.45, 21.917) -> (-30.45, 22.7971)
  curve K6 (-30.45, 21.917) -> (-30.5658, 21.8559)
  curve K7 (-30.5658, 21.8559) -> (-30.6853, 21.9152)
  line L9 (-30.6853, 23.0314) -> (-30.6853, 21.9152)
  curve K8 (-30.6853, 23.0314) -> (-30.5653, 23.1206)
  curve K9 (-30.5653, 23.1206) -> (-30.3912, 23.0572)
  line L10 (-29.9868, 22.6606) -> (-30.3912, 23.0572)
  curve K10 (-29.9868, 22.6606) -> (-29.2184, 22.2382)
  curve K11 (-29.2184, 22.2382) -> (-28.8912, 22.5783)
  curve K12 (-28.8912, 22.5783) -> (-29.0676, 23.0448)
  curve K13 (-29.0676, 23.0448) -> (-28.9459, 23.0912)
  curve K14 (-28.9459, 23.0912) -> (-28.6559, 22.5342)
  curve K15 (-28.6559, 22.5342) -> (-29.1752, 21.9441)
  line L11 (-28.9206, 21.1206) -> (-28.9206, 20.4115)
  line L12 (-29.4904, 21.1206) -> (-28.9206, 21.1206)
  curve K16 (-29.4904, 21.1206) -> (-29.4794, 20.8917)
  curve K17 (-29.4794, 20.8917) -> (-30.0488, 20.2382)
  curve K18 (-30.0488, 20.2382) -> (-30.7147, 20.9859)
  curve K19 (-30.7147, 20.9859) -> (-30.4918, 21.5029)
  curve K20 (-30.4918, 21.5029) -> (-30.3912, 21.4588)
  curve K21 (-30.3912, 21.4588) -> (-30.5088, 21.0002)
  curve K22 (-30.5088, 21.0002) -> (-30.0768, 20.5324)
  curve K23 (-30.0768, 20.5324) -> (-29.6853, 21.0443)
  curve K24 (-29.6853, 21.0443) -> (-29.7037, 21.3343)
  curve K25 (-29.7037, 21.3343) -> (-29.6058, 21.4147)
  line L13 (-28.7864, 21.4147) -> (-29.6058, 21.4147)
  curve K26 (-28.7864, 21.4147) -> (-28.6853, 21.32)
  line L14 (-28.6853, 20.4156) -> (-28.6853, 21.32)
  curve K27 (-28.6853, 20.4156) -> (-28.8015, 20.3559)
  curve K28 (-28.8015, 20.3559) -> (-28.9206, 20.4115)
  curve K29 (-28.9206, 19.9795) -> (-28.8048, 20.0324)
  curve K30 (-28.8048, 20.0324) -> (-28.6853, 19.9786)
  line L15 (-28.6853, 18.5567) -> (-28.6853, 19.9786)
  curve K31 (-28.6853, 18.5567) -> (-28.8048, 18.5029)
  curve K32 (-28.8048, 18.5029) -> (-28.9206, 18.5558)
  line L16 (-28.9206, 19.1206) -> (-28.9206, 18.5558)
  line L17 (-30.6366, 19.1206) -> (-28.9206, 19.1206)
  curve K33 (-30.6366, 19.1206) -> (-30.6853, 19.2676)
  curve K34 (-30.6853, 19.2676) -> (-30.6366, 19.4147)
  line L18 (-28.9206, 19.4147) -> (-30.6366, 19.4147)
  line L19 (-28.9206, 19.9795) -> (-28.9206, 19.4147)
  line L20 (-13.6481, 21.55) -> (-12.1225, 21.55)
  line L21 (-7.6286, 21.55) -> (-12.1225, 21.55)
  line L22 (-22.6481, 21.55) -> (-22.3714, 21.55)
  line L23 (-22.3714, 20.25) -> (-22.6481, 20.25)
  curve K35 (-20.9061, 15.9497) -> (-20.7804, 15.8778)
  curve K36 (-20.7804, 15.8778) -> (-20.7055, 15.834)
  curve K37 (-20.7055, 15.834) -> (-20.5089, 15.7158)
  curve K38 (-20.3691, 15.6286) -> (-20.5089, 15.7158)
  curve K39 (-20.3691, 15.6286) -> (-20.1992, 15.5192)
  curve K40 (-20.1297, 15.4733) -> (-19.9629, 15.3604)
  curve K41 (-19.835, 15.271) -> (-19.9629, 15.3604)
  curve K42 (-19.835, 15.271) -> (-19.6704, 15.1525)
  curve K43 (-19.6087, 15.1071) -> (-19.4842, 15.0134)
  line L24 (-17.9826, 20.25) -> (-17.8775, 20.25)
  line L25 (-22.3714, 20.25) -> (-17.9826, 20.25)
  line L26 (-16.3519, 20.25) -> (-17.8775, 20.25)
  curve K44 (-37.8076, 20.525) -> (-39.3959, 19.7143)
  curve K45 (-33.8076, 20.525) -> (-35.3959, 19.7143)
  line L27 (-17.8825, 21.55) -> (-22.3714, 21.55)
  line L28 (-39, 24.25) -> (-27, 24.25)
  line L29 (-39, 17.55) -> (-27, 17.55)
  line L30 (-12.1225, 20.25) -> (-7.6286, 20.25)
  line L31 (-12.1225, 20.25) -> (-13.6481, 20.25)
  line L32 (-17.8775, 21.55) -> (-17.8825, 21.55)
  line L33 (-17.8775, 21.55) -> (-16.3519, 21.55)
  line L34 (-39, 15.55) -> (-27, 15.55)
  line L35 (-39, 26.25) -> (-27, 26.25)
  curve K46 (-20.8007, 13.501) -> (-20.6962, 13.4225)
  curve K47 (-20.8524, 13.5392) -> (-20.8007, 13.501)
  curve K48 (-20.9904, 13.6385) -> (-20.8524, 13.5392)
  curve K49 (-20.9904, 13.6385) -> (-21.0977, 13.7135)
  curve K50 (-21.2375, 13.8082) -> (-21.0977, 13.7135)
  curve K51 (-21.2958, 13.8467) -> (-21.2375, 13.8082)
  curve K52 (-21.4384, 13.9385) -> (-21.2958, 13.8467)
  curve K53 (-21.4384, 13.9385) -> (-21.5556, 14.0116)
  curve K54 (-21.7205, 14.1108) -> (-21.5556, 14.0116)
  curve K55 (-21.7833, 14.1474) -> (-21.7205, 14.1108)
  curve K56 (-21.8888, 14.2078) -> (-21.7833, 14.1474)
  line L36 (-15, 15.55) -> (-55, 15.55)
  line L37 (-55, 26.25) -> (-15, 26.25)
  line L38 (-15, 20.9) -> (-55, 20.9)
  arc A1 centre (-15, 20.9) radius 7.2 clockwise from (-19.363, 26.6275) to (-7.8294, 21.55)
  arc A2 centre (-27, 36.6528) radius 12.6028 clockwise from (-19.363, 26.6275) to (-27, 24.05)
  arc A3 centre (-39, 20.9) radius 3.15 clockwise from (-39, 17.75) to (-39, 24.05)
  arc A4 centre (-27, 5.1472) radius 12.6028 clockwise from (-27, 17.75) to (-19.363, 15.1725)
  arc A5 centre (-15, 20.9) radius 7.2 clockwise from (-7.8294, 20.25) to (-19.363, 15.1725)
  arc A6 centre (-15, 20.9) radius 3.95 clockwise from (-11.1038, 20.25) to (-18.8962, 20.25)
  arc A7 centre (-24, 20.9) radius 1.5 clockwise from (-22.6481, 20.25) to (-22.6481, 21.55)
  arc A8 centre (-15, 20.9) radius 3.95 clockwise from (-18.8962, 21.55) to (-11.1038, 21.55)
  arc A9 centre (-35, 20.9) radius 1.5206 clockwise from (-34.4103, 22.3016) to (-33.5903, 21.4702)
  arc A10 centre (-35, 20.9) radius 1.25 clockwise from (-35, 19.65) to (-36.25, 20.9)
  arc A11 centre (-39, 20.9) radius 1.5206 clockwise from (-38.4103, 22.3016) to (-37.5903, 21.4702)
  arc A12 centre (-39, 20.9) radius 1.25 clockwise from (-39, 19.65) to (-40.25, 20.9)
  arc A13 centre (-15, 20.9) radius 7.4 clockwise from (-17.6, 27.8282) to (-7.6286, 21.55)
  arc A14 centre (-15, 20.9) radius 7.4 clockwise from (-19.4842, 26.7866) to (-17.6, 27.8282)
  arc A15 centre (-24, 20.9) radius 1.5 clockwise from (-22.6481, 20.25) to (-22.6481, 21.55)
  arc A16 centre (-27, 5.1472) radius 12.4028 clockwise from (-27, 17.55) to (-20.9061, 15.9497)
  closed curve K57 centre (-20.1002, 15.3064)
  closed curve K58 centre (-20.2285, 15.4043)
  arc A17 centre (-15, 20.9) radius 7.4 clockwise from (-12.4, 13.9718) to (-19.4842, 15.0134)
  arc A18 centre (-15, 20.9) radius 7.4 clockwise from (-8.0718, 18.3) to (-12.4, 13.9718)
  arc A19 centre (-15, 20.9) radius 7.4 clockwise from (-7.6286, 20.25) to (-8.0718, 18.3)
  arc A20 centre (-35, 20.9) radius 1.25 clockwise from (-33.8076, 20.525) to (-35.3959, 19.7143)
  arc A21 centre (-39, 20.9) radius 1.25 clockwise from (-37.8076, 20.525) to (-39.3959, 19.7143)
  arc A22 centre (-15, 20.9) radius 1.5 clockwise from (-16.3519, 21.55) to (-13.6481, 21.55)
  arc A23 centre (-15, 20.9) radius 1.5 clockwise from (-13.6481, 20.25) to (-16.3519, 20.25)
  arc A24 centre (-27, 36.6528) radius 12.4028 clockwise from (-19.4842, 26.7866) to (-23.4, 24.784)
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  point P75 (-15, 20.9)
  point P160 (-15, 20.9)
  point P108 (-35, 20.9)
  point P161 (-35, 20.9)
  parallel L36 L37
  coincident P75 P160
  parallel L31 L38
  coincident P108 P161
  midpoint L38 P161
  dimension "d98" = 2
  dimension "d99" diameter = 3.1
  dimension "d100" diameter = 3.75
  dimension "d106" diameter = 17.5
extrude "Extrude15" new body sketch "Sketch13" against normal blind 5.9
extrude "Extrude16" add sketch "Sketch13" along normal blind 1.35
work_plane "WorkPlane5"
sketch "Sketch14" plane through (0, -80.325, 0) normal (0, -1, 0) x axis (1, 0, 0)
  curve K1 (-30.1237, 22.4749) -> (-29.1752, 21.9441)
  line L1 (-30.45, 22.7971) -> (-30.1237, 22.4749)
  line L2 (-30.45, 21.917) -> (-30.45, 22.7971)
  curve K2 (-30.5658, 21.8559) -> (-30.45, 21.917)
  curve K3 (-30.6853, 21.9152) -> (-30.5658, 21.8559)
  line L3 (-30.6853, 23.0314) -> (-30.6853, 21.9152)
  curve K4 (-30.5653, 23.1206) -> (-30.6853, 23.0314)
  curve K5 (-30.3912, 23.0572) -> (-30.5653, 23.1206)
  line L4 (-29.9868, 22.6606) -> (-30.3912, 23.0572)
  curve K6 (-29.2184, 22.2382) -> (-29.9868, 22.6606)
  curve K7 (-28.8912, 22.5783) -> (-29.2184, 22.2382)
  curve K8 (-29.0676, 23.0448) -> (-28.8912, 22.5783)
  curve K9 (-28.9459, 23.0912) -> (-29.0676, 23.0448)
  curve K10 (-28.6559, 22.5342) -> (-28.9459, 23.0912)
  curve K11 (-29.1752, 21.9441) -> (-28.6559, 22.5342)
  line L5 (-28.9206, 21.1206) -> (-28.9206, 20.4115)
  line L6 (-29.4904, 21.1206) -> (-28.9206, 21.1206)
  curve K12 (-29.4794, 20.8917) -> (-29.4904, 21.1206)
  curve K13 (-30.0488, 20.2382) -> (-29.4794, 20.8917)
  curve K14 (-30.7147, 20.9859) -> (-30.0488, 20.2382)
  curve K15 (-30.4918, 21.5029) -> (-30.7147, 20.9859)
  curve K16 (-30.3912, 21.4588) -> (-30.4918, 21.5029)
  curve K17 (-30.5088, 21.0002) -> (-30.3912, 21.4588)
  curve K18 (-30.0768, 20.5324) -> (-30.5088, 21.0002)
  curve K19 (-29.6853, 21.0443) -> (-30.0768, 20.5324)
  curve K20 (-29.7037, 21.3343) -> (-29.6853, 21.0443)
  curve K21 (-29.6058, 21.4147) -> (-29.7037, 21.3343)
  line L7 (-28.7864, 21.4147) -> (-29.6058, 21.4147)
  curve K22 (-28.6853, 21.32) -> (-28.7864, 21.4147)
  line L8 (-28.6853, 20.4156) -> (-28.6853, 21.32)
  curve K23 (-28.8015, 20.3559) -> (-28.6853, 20.4156)
  curve K24 (-28.9206, 20.4115) -> (-28.8015, 20.3559)
  curve K25 (-30.6366, 19.4147) -> (-30.6853, 19.2676)
  line L9 (-28.9206, 19.4147) -> (-30.6366, 19.4147)
  line L10 (-28.9206, 19.9795) -> (-28.9206, 19.4147)
  curve K26 (-28.8048, 20.0324) -> (-28.9206, 19.9795)
  curve K27 (-28.6853, 19.9786) -> (-28.8048, 20.0324)
  line L11 (-28.6853, 18.5567) -> (-28.6853, 19.9786)
  curve K28 (-28.8048, 18.5029) -> (-28.6853, 18.5567)
  curve K29 (-28.9206, 18.5558) -> (-28.8048, 18.5029)
  line L12 (-28.9206, 19.1206) -> (-28.9206, 18.5558)
  line L13 (-30.6366, 19.1206) -> (-28.9206, 19.1206)
  curve K30 (-30.6853, 19.2676) -> (-30.6366, 19.1206)
  line L14 (-15, 15.55) -> (-48.0761, 15.55)
  line L15 (-48.0761, 26.25) -> (-15, 26.25)
  line L16 (-74.9679, 20.9) -> (-15, 20.9)
  line L17 (-55, 20.9) -> (-74.9679, 20.9)
  line L18 (-55, 23.9) -> (-55, 20.9)
  line L19 (-74.9679, 23.9) -> (-55, 23.9)
  line L20 (-74.9679, 20.9) -> (-74.9679, 23.9)
  circle C1 centre (-35, 20.9) radius 1.55
  circle C2 centre (-39, 20.9) radius 1.55
  circle C3 centre (-15, 20.9) radius 1.875
  arc A1 centre (-15, 20.9) radius 5.35 clockwise from (-15, 26.25) to (-15, 15.55)
  circle C4 centre (-55, 20.9) radius 5
  arc A2 centre (-55, 20.9) radius 8.75 clockwise from (-48.0761, 15.55) to (-48.0761, 26.25)
  point P47 (-15, 20.9)
  point P54 (-15, 20.9)
  coincident P47 P54
  horizontal L16
  horizontal L17
  vertical L18
  horizontal L19
  vertical L20
  dimension "d105" diameter C4 = 10
  dimension "d107" distance L16 L19 = 3
revolve "Revolve3" sketch "Sketch14" AlongAngle 360
sketch "Sketch15" plane through (0, -80.325, 0) normal (0, -1, 0) x axis (-1, 0, 0)
  line L1 (75.8988, -124.9) -> (69.8988, -124.9)
  line L2 (74.9679, -23.9) -> (74.9679, -17.9)
  line L3 (59, -17.9) -> (74.9679, -17.9)
  line L4 (59, -23.9) -> (74.9679, -23.9)
  line L5 (55, -131.8586) -> (55, -20.9)
  line L6 (55, -20.9) -> (72.8988, -120.9)
  arc A1 centre (72.8988, -120.9) radius 5 clockwise from (69.8988, -124.9) to (75.8988, -124.9)
  arc A2 centre (55, -20.9) radius 5 clockwise from (59, -23.9) to (59, -17.9)
  point P9 (55, -20.9)
  point P10 (55, -20.9)
  point P4 (72.8988, -120.9)
  point P12 (72.8988, -120.9)
  point P13 (55, -20.9)
  coincident P9 P10
  vertical L5
  coincident P4 P12
  coincident P9 P13
  dimension "d109" angle L5 L6 = 10.148
sketch "Sketch16" plane through (0, 0, 120.9) normal (0, 0, -1) x axis (-1, 0, 0)
  line L1 (74.9679, -83.325) -> (74.9679, -80.325)
  line L2 (74.9679, -80.325) -> (74.9679, -77.325)
  line L3 (59, -77.325) -> (74.9679, -77.325)
  line L4 (59, -83.325) -> (74.9679, -83.325)
  line L5 (72.8988, -59.4086) -> (55, -80.325)
  line L6 (55, -44.342) -> (55, -80.325)
  line L7 (89.2604, -80.325) -> (55, -80.325)
  circle C1 centre (72.8988, -59.4086) radius 5
  arc A1 centre (55, -80.325) radius 5 clockwise from (59, -83.325) to (59, -77.325)
  point P8 (55, -80.325)
  point P9 (55, -80.325)
  point P2 (72.8988, -59.4086)
  point P10 (72.8988, -59.4086)
  point P11 (55, -80.325)
  coincident P8 P9
  coincident P2 P10
  coincident P8 P11
  vertical L6
  perpendicular L6 L7
  dimension "d110" angle L5 L7 = 49.445
  dimension "d111" angle L5 L6 = 40.555
sketch "Sketch17" plane through (0, 0, 30.7) normal (0, 0, 1) x axis (1, 0, 0)
work_plane "WorkPlane6" AlongDistance 0
sketch "Sketch18" plane through (0, 0, 20.9) normal (0, 0, -1) x axis (-1, 0, 0)
  line L1 (17.6191, -80) -> (12.3809, -80)
  line L2 (16.9, -80) -> (13.1, -80)
  line L3 (55, -80.325) -> (15, -80)
  line L4 (72.8988, -59.4086) -> (55, -80.325)
  line L5 (15, -80) -> (72.8988, -59.4086)
  point P7 (15, -80)
  point P6 (55, -80.325)
  point P8 (55, -80.325)
  point P9 (72.8988, -59.4086)
  point P10 (72.8988, -59.4086)
  midpoint L1 P7
  coincident P6 P8
  coincident P9 P10
work_plane "WorkPlane7"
